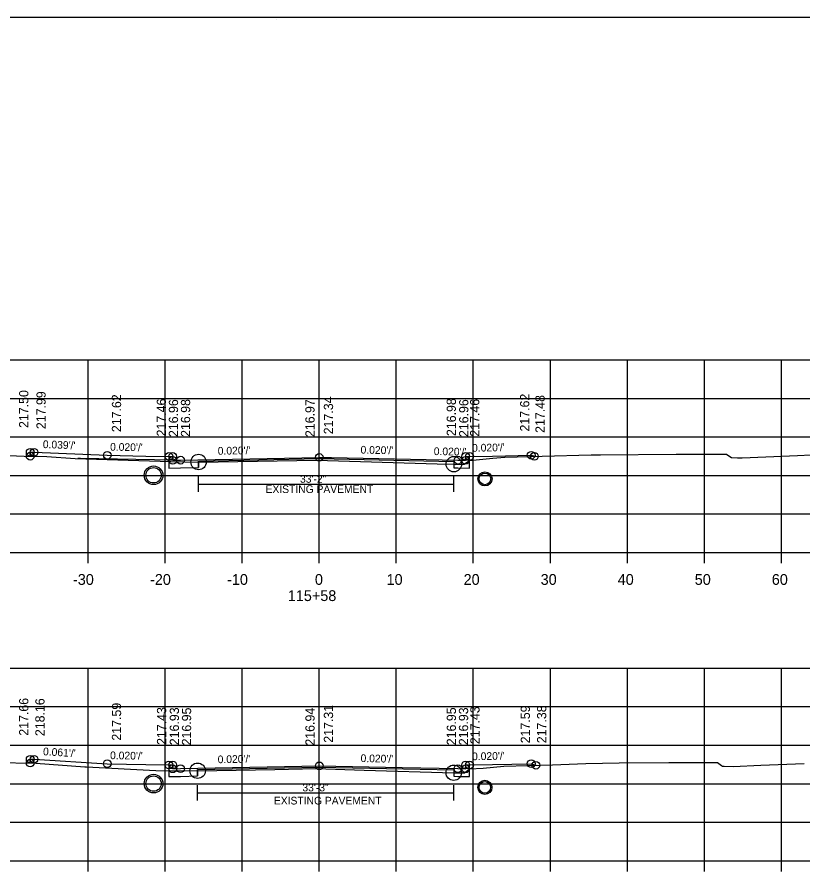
# Model space of a CAD drawing. Extents: x 1368968 to 1369915, y 377395 to 380381.
# Drawn here: x 1369712.6 to 1369814.5, y 378772.6 to 378884.2 of the extents above; entities that cross this region are included whole.
import ezdxf

# ---------------------------------------------------------------- set-up
doc = ezdxf.new("R2010")
doc.units = 0
for name, color, linetype in [('Default', 7, 'Continuous'), ('S_BORDER_NO_PLOT', 7, 'Continuous'), ('S_BREAKLINE_ANNOT', 7, 'Continuous'), ('S_BRIDGE', 7, 'Continuous'), ('S_BRIDGE_ANNOT', 7, 'Continuous'), ('S_CROSS_DRAIN', 7, 'Continuous'), ('S_CTL_TABLE', 7, 'Continuous'), ('S_CURB_ANNOT', 7, 'Continuous'), ('S_DITCHLINE_ANNOT', 7, 'Continuous'), ('S_DROP_INLET', 7, 'Continuous'), ('S_EXIST_ROW_ANNOT', 7, 'Continuous'), ('S_EXISTING_ALIGNMENT_ANNOT', 7, 'Continuous'), ('S_FENCE', 7, 'Continuous')]:
    doc.layers.add(name, color=color, linetype=linetype)

msp = doc.modelspace()

# ---------------------------------------------------------------- linework, layer by layer
at = {"layer": 'Default'}
for p, q in [((1369736.12, 378826.56), (1369736.12, 378825.73)), ((1369736, 378786.53), (1369736, 378785.7))]:
    msp.add_line(p, q, dxfattribs=at)
at = {"layer": 'S_BORDER_NO_PLOT'}
for points in [[(1369732.27, 378827.16), (1369732.28, 378825.66), (1369733.78, 378825.69), (1369736.12, 378825.73), (1369736.12, 378826.56), (1369751.78, 378826.88), (1369769.26, 378826.53), (1369769.26, 378825.7), (1369769.78, 378825.69), (1369771.28, 378825.66), (1369771.29, 378827.16)], [(1369732.27, 378787.13), (1369732.28, 378785.62), (1369733.78, 378785.65), (1369736, 378785.7), (1369736, 378786.53), (1369751.78, 378786.84), (1369769.24, 378786.49), (1369769.24, 378785.66), (1369769.78, 378785.65), (1369771.28, 378785.62), (1369771.29, 378787.13)]]:
    msp.add_lwpolyline(points, dxfattribs=at)
at = {"layer": 'S_BREAKLINE_ANNOT'}
for p, q in [((1369611.78, 378814.7), (1369891.78, 378814.7)), ((1369721.78, 378813.3), (1369721.78, 378814.7)), ((1369731.78, 378813.3), (1369731.78, 378814.7)), ((1369741.78, 378813.3), (1369741.78, 378814.7)), ((1369751.78, 378813.3), (1369751.78, 378814.7)), ((1369761.78, 378813.3), (1369761.78, 378814.7)), ((1369771.78, 378813.3), (1369771.78, 378814.7)), ((1369781.78, 378813.3), (1369781.78, 378814.7)), ((1369791.78, 378813.3), (1369791.78, 378814.7)), ((1369801.78, 378813.3), (1369801.78, 378814.7)), ((1369811.78, 378813.3), (1369811.78, 378814.7)), ((1369611.78, 378774.7), (1369891.78, 378774.7)), ((1369721.78, 378773.3), (1369721.78, 378774.7)), ((1369731.78, 378773.3), (1369731.78, 378774.7)), ((1369741.78, 378773.3), (1369741.78, 378774.7)), ((1369751.78, 378773.3), (1369751.78, 378774.7)), ((1369761.78, 378773.3), (1369761.78, 378774.7)), ((1369771.78, 378773.3), (1369771.78, 378774.7)), ((1369781.78, 378773.3), (1369781.78, 378774.7)), ((1369791.78, 378773.3), (1369791.78, 378774.7)), ((1369801.78, 378773.3), (1369801.78, 378774.7)), ((1369811.78, 378773.3), (1369811.78, 378774.7))]:
    msp.add_line(p, q, dxfattribs=at)
at = {"layer": 'S_BRIDGE_ANNOT'}
for p, q in [((1369593.78, 378884.16), (1369909.96, 378884.16)), ((1369746.3, 378883.9), (1369746.3, 378883.9)), ((1369746.3, 378883.9), (1369746.3, 378883.9))]:
    msp.add_line(p, q, dxfattribs=at)
at = {"layer": 'S_CROSS_DRAIN'}
for p, q in [((1369720.78, 378826.91), (1369720.47, 378826.88)), ((1369732.78, 378826.67), (1369720.78, 378826.91)), ((1369736.12, 378823.57), (1369762.44, 378823.57)), ((1369736.12, 378823.57), (1369769.25, 378823.57)), ((1369736, 378783.51), (1369762.32, 378783.51)), ((1369736, 378783.51), (1369769.24, 378783.51))]:
    msp.add_line(p, q, dxfattribs=at)
at = {"layer": 'S_CTL_TABLE'}
for points in [[(1369706.44, 378827.5), (1369713.48, 378827.21), (1369716.43, 378827.17), (1369720.11, 378826.9), (1369732.52, 378826.52), (1369736.12, 378826.44), (1369738.65, 378826.47), (1369751.41, 378826.69), (1369767.08, 378826.22), (1369769.25, 378826.16), (1369769.45, 378826.14), (1369770.65, 378826.16), (1369770.73, 378826.23), (1369771.3, 378826.63), (1369774.3, 378826.93), (1369775.89, 378827.07), (1369780.72, 378827.21), (1369787.07, 378827.38), (1369788.27, 378827.39), (1369798.12, 378827.45), (1369800.14, 378827.47), (1369804.66, 378827.47), (1369804.94, 378827.26), (1369805.28, 378827.02), (1369806.07, 378827), (1369806.68, 378826.98), (1369813.84, 378827.29), (1369815.65, 378827.38)], [(1369709.73, 378787.43), (1369714.98, 378787.36), (1369721.36, 378786.89), (1369721.41, 378786.88), (1369721.46, 378786.88), (1369721.5, 378786.87), (1369721.56, 378786.87), (1369730.56, 378786.4), (1369736, 378786.38), (1369746.01, 378786.55), (1369751.39, 378786.66), (1369757.61, 378786.47), (1369769.24, 378786.12), (1369769.8, 378786.1), (1369770.64, 378786.11), (1369771.04, 378786.39), (1369771.29, 378786.61), (1369773.04, 378786.72), (1369775.76, 378786.96), (1369782.07, 378787.15), (1369786.4, 378787.31), (1369790.71, 378787.41), (1369797.17, 378787.45), (1369800.68, 378787.43), (1369803.49, 378787.43), (1369804, 378787.04), (1369804.1, 378786.97), (1369804.33, 378786.96), (1369805.51, 378786.93), (1369809.09, 378787.09), (1369814.74, 378787.33)]]:
    msp.add_lwpolyline(points, dxfattribs=at)
at = {"layer": 'S_CURB_ANNOT'}
for points in [[(1369714.27, 378827.2), (1369714.27, 378827.7), (1369714.77, 378827.7), (1369724.27, 378827.32), (1369729.27, 378827.22), (1369732.27, 378827.16), (1369732.39, 378827.16), (1369732.77, 378827.16), (1369732.78, 378826.66), (1369733.78, 378826.68), (1369751.78, 378827.04), (1369753.36, 378827.01), (1369769.77, 378826.68), (1369769.78, 378826.68), (1369770.78, 378826.66), (1369770.79, 378827.16), (1369771.12, 378827.16), (1369771.29, 378827.16), (1369774.29, 378827.22), (1369779.29, 378827.32), (1369779.71, 378827.18)], [(1369714.27, 378787.37), (1369714.27, 378787.87), (1369714.77, 378787.87), (1369724.27, 378787.29), (1369729.27, 378787.19), (1369732.27, 378787.13), (1369732.65, 378787.13), (1369732.77, 378787.13), (1369732.78, 378786.63), (1369733.78, 378786.65), (1369751.78, 378787.01), (1369751.78, 378787.01), (1369762.56, 378786.8), (1369769.78, 378786.65), (1369770.78, 378786.63), (1369770.79, 378787.13), (1369770.97, 378787.13), (1369771.29, 378787.13), (1369774.29, 378787.19), (1369779.29, 378787.29), (1369779.9, 378787.09)]]:
    msp.add_lwpolyline(points, dxfattribs=at)
at = {"layer": 'S_DITCHLINE_ANNOT'}
for p, q in [((1369611.78, 378839.7), (1369891.78, 378839.7)), ((1369721.78, 378814.7), (1369721.78, 378839.7)), ((1369731.78, 378814.7), (1369731.78, 378839.7)), ((1369741.78, 378814.7), (1369741.78, 378839.7)), ((1369751.78, 378814.7), (1369751.78, 378839.7)), ((1369761.78, 378814.7), (1369761.78, 378839.7)), ((1369771.78, 378814.7), (1369771.78, 378839.7)), ((1369781.78, 378814.7), (1369781.78, 378839.7)), ((1369791.78, 378814.7), (1369791.78, 378839.7)), ((1369801.78, 378814.7), (1369801.78, 378839.7)), ((1369811.78, 378814.7), (1369811.78, 378839.7)), ((1369611.78, 378834.7), (1369891.78, 378834.7)), ((1369611.78, 378829.7), (1369891.78, 378829.7)), ((1369611.78, 378824.7), (1369891.78, 378824.7)), ((1369611.78, 378819.7), (1369891.78, 378819.7)), ((1369611.78, 378814.7), (1369891.78, 378814.7)), ((1369611.78, 378799.7), (1369891.78, 378799.7)), ((1369721.78, 378774.7), (1369721.78, 378799.7)), ((1369731.78, 378774.7), (1369731.78, 378799.7)), ((1369741.78, 378774.7), (1369741.78, 378799.7)), ((1369751.78, 378774.7), (1369751.78, 378799.7)), ((1369761.78, 378774.7), (1369761.78, 378799.7)), ((1369771.78, 378774.7), (1369771.78, 378799.7)), ((1369781.78, 378774.7), (1369781.78, 378799.7)), ((1369791.78, 378774.7), (1369791.78, 378799.7)), ((1369801.78, 378774.7), (1369801.78, 378799.7)), ((1369811.78, 378774.7), (1369811.78, 378799.7)), ((1369611.78, 378794.7), (1369891.78, 378794.7)), ((1369611.78, 378789.7), (1369891.78, 378789.7)), ((1369611.78, 378784.7), (1369891.78, 378784.7)), ((1369611.78, 378779.7), (1369891.78, 378779.7)), ((1369611.78, 378774.7), (1369891.78, 378774.7))]:
    msp.add_line(p, q, dxfattribs=at)
at = {"layer": 'S_DROP_INLET'}
msp.add_lwpolyline([(1369827.7, 378884.16), (1369827.7, 378874.28), (1369863.43, 378874.28), (1369863.43, 378871.36), (1369886.63, 378871.36), (1369886.63, 378847.03), (1369909.96, 378847.03), (1369909.96, 378678.7), (1369593.78, 378678.7), (1369593.78, 378884.16)], close=True, dxfattribs=at)
for centre, radius in [((1369714.27, 378827.7), 0.5), ((1369714.77, 378827.7), 0.5), ((1369714.27, 378827.2), 0.5), ((1369724.27, 378827.32), 0.5), ((1369732.27, 378827.16), 0.5), ((1369732.77, 378827.16), 0.5), ((1369732.78, 378826.66), 0.5), ((1369733.78, 378826.68), 0.5), ((1369733.78, 378826.68), 0.5), ((1369736.12, 378826.44), 1), ((1369751.78, 378827.04), 0.5), ((1369769.25, 378826.16), 1), ((1369769.78, 378826.68), 0.5), ((1369769.78, 378826.68), 0.5), ((1369770.78, 378826.66), 0.5), ((1369770.79, 378827.16), 0.5), ((1369771.29, 378827.16), 0.5), ((1369779.29, 378827.32), 0.5), ((1369779.71, 378827.18), 0.5), ((1369730.28, 378824.72), 1.21), ((1369773.29, 378824.25), 0.917), ((1369714.27, 378787.87), 0.5), ((1369714.27, 378787.37), 0.5), ((1369714.77, 378787.87), 0.5), ((1369724.27, 378787.29), 0.5), ((1369779.29, 378787.29), 0.5), ((1369732.27, 378787.13), 0.5), ((1369732.77, 378787.13), 0.5), ((1369732.78, 378786.63), 0.5), ((1369733.78, 378786.65), 0.5), ((1369733.78, 378786.65), 0.5), ((1369736, 378786.38), 1), ((1369751.78, 378787.01), 0.5), ((1369769.24, 378786.12), 1), ((1369769.78, 378786.65), 0.5), ((1369769.78, 378786.65), 0.5), ((1369770.78, 378786.63), 0.5), ((1369770.79, 378787.13), 0.5), ((1369771.29, 378787.13), 0.5), ((1369779.9, 378787.09), 0.5), ((1369730.28, 378784.71), 1.21), ((1369773.28, 378784.22), 0.917)]:
    msp.add_circle(centre, radius, dxfattribs=at)
at = {"layer": 'S_EXIST_ROW_ANNOT'}
for p, q in [((1369736.12, 378822.57), (1369736.12, 378824.57)), ((1369736.12, 378822.57), (1369736.12, 378824.57)), ((1369769.25, 378822.57), (1369769.25, 378824.57)), ((1369736, 378782.51), (1369736, 378784.51)), ((1369736, 378782.51), (1369736, 378784.51)), ((1369769.24, 378782.51), (1369769.24, 378784.51))]:
    msp.add_line(p, q, dxfattribs=at)
for centre, radius in [((1369730.28, 378824.72), 1), ((1369773.29, 378824.25), 0.75), ((1369730.28, 378784.71), 1), ((1369773.28, 378784.22), 0.75)]:
    msp.add_circle(centre, radius, dxfattribs=at)
at = {"layer": 'S_EXISTING_ALIGNMENT_ANNOT'}
for p, q in [((1369751.78, 378826.68), (1369751.78, 378836.68)), ((1369751.78, 378786.64), (1369751.78, 378796.64))]:
    msp.add_line(p, q, dxfattribs=at)

# ---------------------------------------------------------------- texts
at = {"layer": 'S_BRIDGE'}
for s, p in [('-30', (1369719.82, 378810.5)), ('-20', (1369729.82, 378810.5)), ('-10', (1369739.82, 378810.5)), ('0', (1369751.22, 378810.5)), ('10', (1369760.52, 378810.5)), ('20', (1369770.52, 378810.5)), ('30', (1369780.52, 378810.5)), ('40', (1369790.52, 378810.5)), ('50', (1369800.52, 378810.5)), ('60', (1369810.52, 378810.5)), ('115+58', (1369747.7, 378808.4))]:
    msp.add_text(s, height=1.4, dxfattribs=at).set_placement(p)
at = {"layer": 'S_EXIST_ROW_ANNOT'}
for s, p in [('33\'-2"', (1369749.29, 378823.75)), ('EXISTING PAVEMENT', (1369744.82, 378822.42)), ('33\'-3"', (1369749.6, 378783.7)), ('EXISTING PAVEMENT', (1369745.9, 378782))]:
    msp.add_text(s, height=1, dxfattribs=at).set_placement(p)
at = {"layer": 'S_EXISTING_ALIGNMENT_ANNOT'}
for s, p in [('217.50', (1369714.03, 378830.86)), ('217.99', (1369716.28, 378830.71)), ('217.62', (1369726.07, 378830.32)), ('217.34', (1369753.58, 378830.04)), ('216.98', (1369769.52, 378829.81)), ('217.62', (1369779.05, 378830.4)), ('217.48', (1369781.04, 378830.22)), ('217.46', (1369731.89, 378829.76)), ('216.96', (1369733.46, 378829.68)), ('216.98', (1369735.03, 378829.7)), ('216.97', (1369751.18, 378829.68)), ('216.96', (1369771.14, 378829.68)), ('217.46', (1369772.56, 378829.73)), ('217.66', (1369714.03, 378790.92)), ('218.16', (1369716.13, 378790.87)), ('217.59', (1369726.07, 378790.29)), ('217.43', (1369731.92, 378789.73)), ('216.93', (1369733.58, 378789.69)), ('216.95', (1369735.16, 378789.67)), ('216.94', (1369751.18, 378789.64)), ('217.31', (1369753.58, 378790.01)), ('216.95', (1369769.53, 378789.69)), ('216.93', (1369771.11, 378789.69)), ('217.43', (1369772.59, 378789.83)), ('217.59', (1369779.13, 378789.94)), ('217.38', (1369781.25, 378789.95))]:
    msp.add_text(s, height=1.2, rotation=90, dxfattribs=at).set_placement(p)
at = {"layer": 'S_FENCE'}
for s, rotation, p in [("0.039'/'", 357.7397, (1369715.89, 378828.26)), ("0.020'/'", 358.8542, (1369724.63, 378827.92)), ("0.020'/'", 1.1458, (1369738.62, 378827.38)), ("0.020'/'", 358.8542, (1369757.14, 378827.54)), ("0.020'/'", 358.8543, (1369766.64, 378827.35)), ("0.020'/'", 1.1458, (1369771.63, 378827.77)), ("0.061'/'", 356.5365, (1369715.91, 378788.4)), ("0.020'/'", 358.8542, (1369724.63, 378787.89)), ("0.020'/'", 1.1457, (1369771.63, 378787.74)), ("0.020'/'", 1.1458, (1369738.61, 378787.35)), ("0.020'/'", 358.8542, (1369757.14, 378787.51))]:
    msp.add_text(s, height=1, rotation=rotation, dxfattribs=at).set_placement(p)

doc.saveas('drawing.dxf')
